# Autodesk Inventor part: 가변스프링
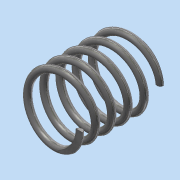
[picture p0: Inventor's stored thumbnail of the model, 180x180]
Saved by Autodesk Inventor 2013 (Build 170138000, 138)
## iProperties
Created: 2018-12
Part Number: 가변스프링
Material: 스테인리스강
Document SubType Name: Modeling
Designer: dgall
Density: 1 g/cm^3
Author: dgall
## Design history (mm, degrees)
sketch "스케치1"
  geometry: L1 (0, 0)-(9, 0); L2 (0, 0)-(0, 24.5); L3 (0, 24.5)-(9, 24.5); C1 r 1 at (9, 0)
  constraints: 6 end point, 2 perpendicular, 1 centre point, 1 coincident, 1 horizontal, 1 vertical alignment
  dimensions: "d0" = 24.5 distance of L1.start L2.end (derived); "d1" = 18 diameter of L1.end L2; "d3" = 2 diameter of C1
feature "코일1" pitch "d4" = 10; turns "d6" = 5; dims "d5" = 24.5 (= d0), "d7" = 0, angle "d8" = 90 deg, angle "d9" = 90 deg, "d10" = 0, "d11" = 0
node "작업 평면2"
  node "작업 평면1"
feature "분할1"
feature "분할2"
node "솔리드1"
other parameters: "d12" = 0, "d13" = 0
